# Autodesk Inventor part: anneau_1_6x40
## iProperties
Created: 2011-01
Part Number: anneau_1_6x40
Document SubType Name: Modeling
Designer: eric
Density: 1 g/cm^3
Mass: 0.252662 g
Surface Area: 6.31655 cm^2
Volume: 0.252662 cm^3
Author: eric
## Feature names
1. Base1
